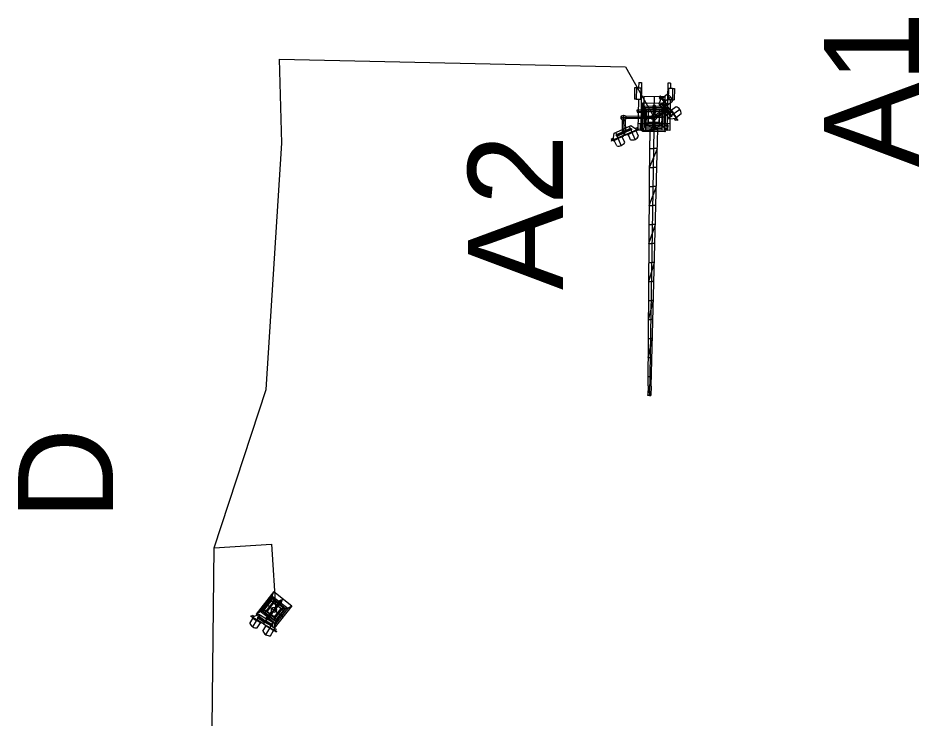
# Model space of a CAD drawing. Extents: x -717079 to -715675, y -957336 to -955099.
# Drawn here: x -716685.49 to -716661.77, y -956457.54 to -956439.09 of the extents above; entities that cross this region are included whole.
import ezdxf

# ---------------------------------------------------------------- set-up
doc = ezdxf.new("R2010")
doc.units = 0
doc.layers.add('TZ_PUPFL', color=7, linetype='Continuous')

msp = doc.modelspace()

# ---------------------------------------------------------------- linework, layer by layer
at = {"layer": 'TZ_PUPFL'}
for p, q in [((-716669.151, -956440.79), (-716669.154, -956440.93)), ((-716669.151, -956440.79), (-716669.076, -956440.791)), ((-716669.076, -956440.791), (-716669.097, -956442.041)), ((-716668.387, -956440.803), (-716668.408, -956442.052)), ((-716668.311, -956440.804), (-716668.387, -956440.803)), ((-716668.311, -956440.804), (-716668.314, -956440.944)), ((-716669.259, -956440.928), (-716669.264, -956441.228)), ((-716669.209, -956440.929), (-716669.259, -956440.928)), ((-716669.209, -956440.929), (-716669.214, -956441.229)), ((-716669.209, -956440.929), (-716669.099, -956440.931)), ((-716669.099, -956440.931), (-716669.104, -956441.231)), ((-716668.369, -956440.943), (-716668.374, -956441.243)), ((-716668.259, -956440.945), (-716668.369, -956440.943)), ((-716668.259, -956440.945), (-716668.264, -956441.245)), ((-716668.259, -956440.945), (-716668.209, -956440.946)), ((-716668.209, -956440.946), (-716668.214, -956441.246)), ((-716669.214, -956441.229), (-716669.264, -956441.228)), ((-716669.214, -956441.229), (-716669.104, -956441.231)), ((-716669.159, -956441.23), (-716669.172, -956442.04)), ((-716669.012, -956441.152), (-716669.021, -956441.692)), ((-716669.012, -956441.152), (-716668.462, -956441.161)), ((-716668.75, -956441.907), (-716668.737, -956441.157)), ((-716668.558, -956441.19), (-716668.625, -956441.363)), ((-716668.575, -956441.166), (-716668.612, -956441.193)), ((-716668.612, -956441.193), (-716668.577, -956441.24)), ((-716668.302, -956441.177), (-716668.601, -956441.395)), ((-716668.594, -956441.142), (-716668.59, -956441.139)), ((-716668.358, -956441.465), (-716668.594, -956441.142)), ((-716668.354, -956441.462), (-716668.59, -956441.139)), ((-716668.555, -956441.187), (-716668.542, -956441.179)), ((-716668.542, -956441.179), (-716668.46, -956441.292)), ((-716668.4, -956441.106), (-716668.528, -956441.199)), ((-716668.462, -956441.161), (-716668.471, -956441.701)), ((-716668.264, -956441.245), (-716668.374, -956441.243)), ((-716668.319, -956441.244), (-716668.332, -956442.054)), ((-716668.264, -956441.245), (-716668.214, -956441.246)), ((-716669.189, -956441.539), (-716669.188, -956441.509)), ((-716669.188, -956441.509), (-716669.018, -956441.512)), ((-716669.053, -956442.076), (-716669.04, -956441.327)), ((-716669.04, -956441.327), (-716668.44, -956441.337)), ((-716669.002, -956441.442), (-716669.04, -956441.327)), ((-716669.017, -956441.402), (-716668.467, -956441.411)), ((-716669.011, -956441.962), (-716669.002, -956441.442)), ((-716669.002, -956441.442), (-716668.782, -956441.446)), ((-716668.963, -956441.483), (-716669.002, -956441.442)), ((-716668.97, -956441.923), (-716668.963, -956441.483)), ((-716668.963, -956441.483), (-716668.778, -956441.486)), ((-716668.946, -956441.693), (-716668.944, -956441.523)), ((-716668.923, -956441.504), (-716668.563, -956441.51)), ((-716668.9, -956441.904), (-716668.893, -956441.504)), ((-716668.9, -956441.904), (-716668.893, -956441.504)), ((-716668.782, -956441.446), (-716668.761, -956441.389)), ((-716668.782, -956441.446), (-716668.765, -956441.631)), ((-716668.761, -956441.389), (-716668.765, -956441.631)), ((-716668.721, -956441.39), (-716668.761, -956441.389)), ((-716668.753, -956442.082), (-716668.74, -956441.332)), ((-716668.752, -956442.047), (-716668.741, -956441.373)), ((-716668.721, -956441.39), (-716668.725, -956441.632)), ((-716668.702, -956441.447), (-716668.725, -956441.632)), ((-716668.722, -956441.645), (-716668.44, -956441.475)), ((-716668.702, -956441.447), (-716668.721, -956441.39)), ((-716668.707, -956441.487), (-716668.523, -956441.491)), ((-716668.702, -956441.451), (-716668.482, -956441.451)), ((-716668.69, -956441.672), (-716668.385, -956441.489)), ((-716668.625, -956441.363), (-716668.484, -956441.556)), ((-716668.6, -956441.909), (-716668.593, -956441.509)), ((-716668.6, -956441.909), (-716668.593, -956441.509)), ((-716668.553, -956441.36), (-716668.435, -956441.521)), ((-716668.289, -956441.687), (-716668.548, -956441.332)), ((-716668.523, -956441.491), (-716668.53, -956441.931)), ((-716668.482, -956441.451), (-716668.523, -956441.491)), ((-716668.521, -956441.336), (-716668.403, -956441.498)), ((-716668.482, -956441.451), (-716668.491, -956441.971)), ((-716668.484, -956441.556), (-716668.354, -956441.462)), ((-716668.44, -956441.337), (-716668.482, -956441.451)), ((-716668.298, -956441.524), (-716668.468, -956441.521)), ((-716668.377, -956441.405), (-716668.46, -956441.292)), ((-716668.453, -956442.087), (-716668.44, -956441.337)), ((-716668.398, -956441.544), (-716668.44, -956441.475)), ((-716668.317, -956441.683), (-716668.435, -956441.521)), ((-716668.285, -956441.659), (-716668.403, -956441.498)), ((-716668.265, -956441.292), (-716668.392, -956441.385)), ((-716668.39, -956441.414), (-716668.377, -956441.405)), ((-716668.067, -956441.5), (-716668.366, -956441.718)), ((-716668.358, -956441.465), (-716668.122, -956441.788)), ((-716668.354, -956441.462), (-716668.119, -956441.785)), ((-716668.319, -956441.511), (-716668.307, -956441.502)), ((-716668.307, -956441.502), (-716668.224, -956441.615)), ((-716668.299, -956441.554), (-716668.298, -956441.524)), ((-716668.165, -956441.429), (-716668.292, -956441.522)), ((-716668.68, -956441.706), (-716669.613, -956441.717)), ((-716669.613, -956441.717), (-716669.48, -956441.716)), ((-716669.547, -956441.65), (-716669.541, -956442.139)), ((-716669.546, -956441.783), (-716669.547, -956441.65)), ((-716668.812, -956441.678), (-716669.488, -956441.686)), ((-716668.811, -956441.738), (-716669.487, -956441.746)), ((-716669.189, -956441.539), (-716668.299, -956441.554)), ((-716669.189, -956441.539), (-716669.189, -956441.569)), ((-716669.189, -956441.569), (-716669.019, -956441.572)), ((-716669.165, -956441.54), (-716668.325, -956441.554)), ((-716668.447, -956441.712), (-716669.046, -956441.702)), ((-716668.812, -956441.696), (-716669.021, -956441.692)), ((-716668.95, -956441.883), (-716668.946, -956441.693)), ((-716668.947, -956441.703), (-716668.547, -956441.71)), ((-716668.947, -956441.703), (-716668.547, -956441.71)), ((-716668.544, -956441.56), (-716668.944, -956441.553)), ((-716668.944, -956441.553), (-716668.544, -956441.56)), ((-716668.889, -956441.824), (-716668.886, -956441.694)), ((-716668.69, -956441.672), (-716668.804, -956441.741)), ((-716668.794, -956441.66), (-716668.798, -956441.657)), ((-716668.793, -956441.754), (-716668.797, -956441.758)), ((-716668.712, -956441.764), (-716668.781, -956441.65)), ((-716668.725, -956441.632), (-716668.765, -956441.631)), ((-716668.746, -956441.773), (-716668.747, -956441.64)), ((-716668.686, -956441.663), (-716668.693, -956441.667)), ((-716668.679, -956441.674), (-716668.686, -956441.678)), ((-716668.471, -956441.701), (-716668.681, -956441.698)), ((-716668.68, -956441.714), (-716668.398, -956441.544)), ((-716668.609, -956441.829), (-716668.606, -956441.699)), ((-716668.546, -956441.7), (-716668.55, -956441.89)), ((-716668.544, -956441.53), (-716668.546, -956441.7)), ((-716668.342, -956441.75), (-716668.484, -956441.556)), ((-716668.299, -956441.584), (-716668.469, -956441.581)), ((-716668.158, -956441.74), (-716668.342, -956441.75)), ((-716668.299, -956441.554), (-716668.299, -956441.584)), ((-716668.142, -956441.728), (-716668.224, -956441.615)), ((-716668.177, -956441.79), (-716668.211, -956441.743)), ((-716668.029, -956441.615), (-716668.157, -956441.708)), ((-716668.154, -956441.737), (-716668.142, -956441.728)), ((-716669.586, -956441.77), (-716669.582, -956442.099)), ((-716669.354, -956441.93), (-716669.574, -956442.026)), ((-716669.552, -956441.791), (-716669.552, -956441.783)), ((-716669.539, -956441.791), (-716669.539, -956441.783)), ((-716669.506, -956441.769), (-716669.502, -956442.098)), ((-716669.243, -956442.285), (-716669.39, -956441.946)), ((-716669.2, -956442.033), (-716669.354, -956441.93)), ((-716669.191, -956441.98), (-716669.244, -956442.003)), ((-716669.173, -956442.021), (-716669.191, -956441.98)), ((-716669.169, -956441.86), (-716668.749, -956441.867)), ((-716669.113, -956441.891), (-716669.115, -956442.021)), ((-716669.113, -956441.891), (-716669.092, -956441.871)), ((-716669.011, -956441.962), (-716669.053, -956442.076)), ((-716668.97, -956441.923), (-716669.011, -956441.962)), ((-716668.791, -956441.966), (-716669.011, -956441.962)), ((-716668.786, -956441.926), (-716668.97, -956441.923)), ((-716668.967, -956442.043), (-716668.964, -956441.873)), ((-716668.964, -956441.873), (-716668.944, -956441.873)), ((-716668.549, -956441.86), (-716668.949, -956441.853)), ((-716668.949, -956441.853), (-716668.549, -956441.86)), ((-716668.816, -956441.986), (-716668.944, -956441.873)), ((-716668.57, -956441.91), (-716668.93, -956441.904)), ((-716668.889, -956441.824), (-716668.609, -956441.829)), ((-716668.817, -956442.006), (-716668.816, -956441.986)), ((-716668.791, -956441.966), (-716668.768, -956441.781)), ((-716668.791, -956441.966), (-716668.772, -956442.024)), ((-716668.772, -956442.024), (-716668.768, -956441.781)), ((-716668.728, -956441.782), (-716668.768, -956441.781)), ((-716668.329, -956441.874), (-716668.749, -956441.867)), ((-716668.732, -956442.025), (-716668.728, -956441.782)), ((-716668.711, -956441.967), (-716668.732, -956442.025)), ((-716668.711, -956441.967), (-716668.728, -956441.782)), ((-716668.53, -956441.931), (-716668.715, -956441.927)), ((-716668.491, -956441.971), (-716668.711, -956441.967)), ((-716668.687, -956442.008), (-716668.686, -956441.988)), ((-716668.686, -956441.988), (-716668.554, -956441.88)), ((-716668.534, -956441.88), (-716668.554, -956441.88)), ((-716668.537, -956442.05), (-716668.534, -956441.88)), ((-716668.53, -956441.931), (-716668.491, -956441.971)), ((-716668.491, -956441.971), (-716668.453, -956442.087)), ((-716668.387, -956441.903), (-716668.406, -956441.882)), ((-716668.387, -956441.903), (-716668.389, -956442.033)), ((-716668.14, -956441.763), (-716668.177, -956441.79)), ((-716668.122, -956441.788), (-716668.119, -956441.785)), ((-716669.512, -956442.168), (-716669.879, -956442.327)), ((-716669.51, -956442.172), (-716669.877, -956442.332)), ((-716669.824, -956442.304), (-716669.794, -956442.121)), ((-716669.794, -956442.121), (-716669.574, -956442.026)), ((-716669.61, -956442.445), (-716669.757, -956442.105)), ((-716669.744, -956442.187), (-716669.34, -956442.011)), ((-716669.733, -956442.16), (-716669.55, -956442.081)), ((-716669.717, -956442.197), (-716669.534, -956442.117)), ((-716669.559, -956442.21), (-716669.687, -956442.266)), ((-716669.582, -956442.099), (-716669.502, -956442.098)), ((-716669.519, -956442.364), (-716669.582, -956442.22)), ((-716669.574, -956442.026), (-716669.51, -956442.172)), ((-716669.565, -956442.196), (-716669.559, -956442.21)), ((-716669.366, -956442.001), (-716669.55, -956442.081)), ((-716669.35, -956442.038), (-716669.534, -956442.117)), ((-716669.512, -956442.168), (-716669.145, -956442.009)), ((-716669.51, -956442.172), (-716669.143, -956442.013)), ((-716669.455, -956442.148), (-716669.449, -956442.162)), ((-716669.449, -956442.162), (-716669.321, -956442.106)), ((-716669.363, -956442.297), (-716669.426, -956442.152)), ((-716669.192, -956442.051), (-716669.321, -956442.106)), ((-716669.152, -956442.205), (-716669.215, -956442.061)), ((-716669.198, -956442.037), (-716669.192, -956442.051)), ((-716668.332, -956442.054), (-716669.172, -956442.04)), ((-716669.145, -956442.009), (-716669.143, -956442.013)), ((-716669.115, -956442.021), (-716669.095, -956442.041)), ((-716668.453, -956442.087), (-716669.053, -956442.076)), ((-716668.752, -956442.007), (-716668.868, -956449.026)), ((-716668.857, -956442.025), (-716668.862, -956442.325)), ((-716668.647, -956442.028), (-716668.857, -956442.025)), ((-716668.732, -956442.025), (-716668.772, -956442.024)), ((-716668.652, -956442.328), (-716668.647, -956442.028)), ((-716668.389, -956442.033), (-716668.409, -956442.052)), ((-716669.879, -956442.327), (-716669.877, -956442.332)), ((-716669.869, -956442.274), (-716669.815, -956442.251)), ((-716669.851, -956442.315), (-716669.869, -956442.274)), ((-716669.822, -956442.308), (-716669.816, -956442.321)), ((-716669.816, -956442.321), (-716669.687, -956442.266)), ((-716669.73, -956442.456), (-716669.793, -956442.312)), ((-716668.904, -956448.775), (-716668.862, -956442.325)), ((-716668.824, -956448.776), (-716668.652, -956442.328)), ((-716668.866, -956443.025), (-716668.657, -956442.528)), ((-716668.863, -956442.525), (-716668.76, -956442.527)), ((-716668.657, -956442.528), (-716668.76, -956442.527)), ((-716668.866, -956443.025), (-716668.769, -956443.027)), ((-716668.671, -956443.028), (-716668.769, -956443.027)), ((-716668.873, -956444.025), (-716668.684, -956443.528)), ((-716668.87, -956443.525), (-716668.777, -956443.526)), ((-716668.684, -956443.528), (-716668.777, -956443.526)), ((-716668.873, -956444.025), (-716668.785, -956444.026)), ((-716668.697, -956444.028), (-716668.785, -956444.026)), ((-716668.88, -956445.025), (-716668.711, -956444.528)), ((-716668.876, -956444.525), (-716668.793, -956444.526)), ((-716668.711, -956444.528), (-716668.793, -956444.526)), ((-716668.88, -956445.025), (-716668.802, -956445.026)), ((-716668.724, -956445.028), (-716668.802, -956445.026)), ((-716668.886, -956446.025), (-716668.737, -956445.527)), ((-716668.883, -956445.525), (-716668.81, -956445.526)), ((-716668.737, -956445.527), (-716668.81, -956445.526)), ((-716668.886, -956446.025), (-716668.818, -956446.026)), ((-716668.751, -956446.027), (-716668.818, -956446.026)), ((-716668.893, -956447.025), (-716668.764, -956446.527)), ((-716668.889, -956446.525), (-716668.827, -956446.526)), ((-716668.764, -956446.527), (-716668.827, -956446.526)), ((-716668.893, -956447.025), (-716668.835, -956447.026)), ((-716668.777, -956447.027), (-716668.835, -956447.026)), ((-716668.899, -956448.025), (-716668.791, -956447.527)), ((-716668.896, -956447.525), (-716668.843, -956447.526)), ((-716668.791, -956447.527), (-716668.843, -956447.526)), ((-716668.899, -956448.025), (-716668.852, -956448.026)), ((-716668.804, -956448.027), (-716668.852, -956448.026)), ((-716668.908, -956449.025), (-716668.818, -956448.526)), ((-716668.903, -956448.525), (-716668.86, -956448.526)), ((-716668.818, -956448.526), (-716668.86, -956448.526)), ((-716668.904, -956448.775), (-716668.908, -956449.025)), ((-716668.824, -956448.776), (-716668.828, -956449.026)), ((-716668.868, -956449.026), (-716668.908, -956449.025)), ((-716668.868, -956449.026), (-716668.828, -956449.026)), ((-716678.759, -956454.187), (-716679.221, -956454.778)), ((-716679.119, -956454.712), (-716678.798, -956454.302)), ((-716678.798, -956454.302), (-716678.759, -956454.187)), ((-716678.798, -956454.302), (-716678.625, -956454.438)), ((-716678.791, -956454.358), (-716678.798, -956454.302)), ((-716678.759, -956454.187), (-716678.286, -956454.557)), ((-716679.062, -956454.705), (-716678.791, -956454.358)), ((-716679.022, -956454.686), (-716678.8, -956454.402)), ((-716678.749, -956454.417), (-716678.995, -956454.732)), ((-716678.749, -956454.417), (-716678.995, -956454.732)), ((-716678.99, -956454.482), (-716678.517, -956454.852)), ((-716678.523, -956454.372), (-716678.985, -956454.963)), ((-716678.762, -956454.483), (-716678.934, -956454.704)), ((-716678.911, -956454.544), (-716678.596, -956454.79)), ((-716678.63, -956454.51), (-716678.877, -956454.825)), ((-716678.819, -956454.426), (-716678.504, -956454.672)), ((-716678.819, -956454.426), (-716678.504, -956454.672)), ((-716678.791, -956454.358), (-716678.646, -956454.472)), ((-716678.772, -956454.399), (-716678.623, -956454.516)), ((-716678.762, -956454.483), (-716678.667, -956454.557)), ((-716678.286, -956454.557), (-716678.748, -956455.147)), ((-716678.574, -956454.405), (-716678.723, -956454.596)), ((-716678.625, -956454.438), (-716678.723, -956454.596)), ((-716678.542, -956454.429), (-716678.692, -956454.62)), ((-716678.562, -956454.487), (-716678.692, -956454.62)), ((-716678.573, -956454.631), (-716678.667, -956454.557)), ((-716678.625, -956454.438), (-716678.574, -956454.405)), ((-716678.623, -956454.516), (-716678.489, -956454.62)), ((-716678.59, -956454.516), (-716678.445, -956454.629)), ((-716678.574, -956454.405), (-716678.542, -956454.429)), ((-716678.562, -956454.487), (-716678.542, -956454.429)), ((-716678.562, -956454.487), (-716678.389, -956454.623)), ((-716678.389, -956454.623), (-716678.286, -956454.557)), ((-716679.345, -956454.845), (-716679.323, -956454.806)), ((-716679.323, -956454.806), (-716679.272, -956454.836)), ((-716679.32, -956454.86), (-716679.155, -956454.777)), ((-716679.309, -956455.116), (-716679.12, -956454.798)), ((-716679.221, -956454.778), (-716679.119, -956454.712)), ((-716678.748, -956455.147), (-716679.221, -956454.778)), ((-716679.155, -956454.777), (-716678.948, -956454.9)), ((-716679.119, -956454.712), (-716679.062, -956454.705)), ((-716678.943, -956454.845), (-716679.119, -956454.712)), ((-716678.917, -956454.818), (-716679.062, -956454.705)), ((-716678.869, -956454.831), (-716679.019, -956454.714)), ((-716679.004, -956454.662), (-716678.688, -956454.909)), ((-716679.004, -956454.662), (-716678.688, -956454.909)), ((-716678.965, -956454.905), (-716678.816, -956454.714)), ((-716678.945, -956454.847), (-716678.816, -956454.714)), ((-716678.934, -956454.704), (-716678.84, -956454.777)), ((-716678.933, -956454.93), (-716678.784, -956454.739)), ((-716678.882, -956454.897), (-716678.784, -956454.739)), ((-716678.745, -956454.851), (-716678.84, -956454.777)), ((-716678.816, -956454.714), (-716678.784, -956454.739)), ((-716678.512, -956454.602), (-716678.759, -956454.917)), ((-716678.512, -956454.602), (-716678.759, -956454.917)), ((-716678.573, -956454.631), (-716678.745, -956454.851)), ((-716678.723, -956454.596), (-716678.692, -956454.62)), ((-716678.445, -956454.629), (-716678.716, -956454.976)), ((-716678.389, -956454.623), (-716678.709, -956455.032)), ((-716678.485, -956454.649), (-716678.707, -956454.932)), ((-716678.445, -956454.629), (-716678.389, -956454.623)), ((-716679.389, -956455.025), (-716679.309, -956454.89)), ((-716679.372, -956454.83), (-716679.374, -956454.833)), ((-716679.03, -956455.037), (-716679.374, -956454.833)), ((-716679.028, -956455.033), (-716679.372, -956454.83)), ((-716679.322, -956454.864), (-716679.33, -956454.877)), ((-716679.33, -956454.877), (-716679.21, -956454.948)), ((-716679.089, -956455.02), (-716679.21, -956454.948)), ((-716679.191, -956455.142), (-716679.111, -956455.007)), ((-716679.178, -956454.856), (-716678.8, -956455.081)), ((-716679.171, -956454.884), (-716678.999, -956454.986)), ((-716679.151, -956454.849), (-716678.979, -956454.951)), ((-716679.082, -956455.007), (-716679.089, -956455.02)), ((-716678.948, -956454.9), (-716679.03, -956455.037)), ((-716679.03, -956455.037), (-716678.686, -956455.241)), ((-716679.028, -956455.033), (-716678.684, -956455.237)), ((-716678.827, -956455.088), (-716678.999, -956454.986)), ((-716678.807, -956455.053), (-716678.979, -956454.951)), ((-716678.945, -956454.847), (-716678.965, -956454.905)), ((-716678.965, -956454.905), (-716678.933, -956454.93)), ((-716678.965, -956455.32), (-716678.776, -956455.002)), ((-716678.742, -956455.022), (-716678.948, -956454.9)), ((-716678.882, -956454.897), (-716678.933, -956454.93)), ((-716678.709, -956455.032), (-716678.882, -956454.897)), ((-716678.735, -956454.936), (-716678.869, -956454.831)), ((-716678.716, -956454.976), (-716678.861, -956454.862)), ((-716678.709, -956455.032), (-716678.748, -956455.147)), ((-716678.735, -956455.207), (-716678.742, -956455.022)), ((-716678.716, -956454.976), (-716678.709, -956455.032)), ((-716679.045, -956455.229), (-716678.964, -956455.094)), ((-716678.978, -956455.068), (-716678.986, -956455.081)), ((-716678.986, -956455.081), (-716678.866, -956455.152)), ((-716678.745, -956455.224), (-716678.866, -956455.152)), ((-716678.847, -956455.346), (-716678.767, -956455.211)), ((-716678.737, -956455.211), (-716678.745, -956455.224)), ((-716678.687, -956455.183), (-716678.737, -956455.153)), ((-716678.71, -956455.222), (-716678.687, -956455.183)), ((-716678.684, -956455.237), (-716678.686, -956455.241))]:
    msp.add_line(p, q, dxfattribs=at)
for points in [[(-716682.682, -956485.549), (-716684.309, -956485.117), (-716683.726, -956482.879), (-716679.632, -956479.652), (-716679.258, -956477.256), (-716679.479, -956475.115), (-716680.551, -956472.706), (-716680.325, -956453.033), (-716678.96, -956448.869), (-716678.546, -956442.387), (-716678.608, -956440.175), (-716669.501, -956440.378), (-716668.747, -956441.71)], [(-716669.092, -956441.871), (-716668.964, -956441.873)], [(-716668.406, -956441.882), (-716668.534, -956441.88)], [(-716669.095, -956442.041), (-716668.752, -956442.047)], [(-716668.967, -956442.003), (-716668.752, -956442.007)], [(-716668.537, -956442.01), (-716668.752, -956442.007)], [(-716668.409, -956442.052), (-716668.752, -956442.047)], [(-716682.682, -956485.549), (-716684.309, -956485.117), (-716683.726, -956482.879), (-716679.632, -956479.652), (-716679.258, -956477.256), (-716679.479, -956475.115), (-716680.551, -956472.706), (-716680.325, -956453.033), (-716678.816, -956452.936), (-716678.701, -956454.708)]]:
    msp.add_lwpolyline(points, dxfattribs=at)
for centre, radius in [((-716668.537, -956441.348), 0.02), ((-716669.547, -956441.716), 0.0665), ((-716668.894, -956441.554), 0.0135), ((-716668.747, -956441.707), 0.0665), ((-716668.594, -956441.559), 0.0135), ((-716668.301, -956441.671), 0.02), ((-716669.081, -956441.996), 0.012), ((-716669.08, -956441.916), 0.012), ((-716668.899, -956441.854), 0.0135), ((-716668.599, -956441.859), 0.0135), ((-716668.421, -956442.007), 0.012), ((-716668.42, -956441.927), 0.012), ((-716669.725, -956442.179), 0.02), ((-716669.358, -956442.019), 0.02), ((-716678.779, -956454.457), 0.0135), ((-716678.964, -956454.693), 0.0135), ((-716678.754, -956454.667), 0.0665), ((-716678.543, -956454.641), 0.0135), ((-716679.161, -956454.867), 0.02), ((-716678.728, -956454.878), 0.0135), ((-716678.817, -956455.07), 0.02)]:
    msp.add_circle(centre, radius, dxfattribs=at)
for centre, radius, start, end in [((-716668.46, -956441.292), 0.195, 36.0884, 72.2272), ((-716668.46, -956441.292), 0.195, 359.9496, 36.0884), ((-716668.924, -956441.524), 0.02, 89.0486, 179.0486), ((-716668.564, -956441.53), 0.02, 359.0486, 89.0486), ((-716668.419, -956441.509), 0.04, 301.0656, 121.0656), ((-716668.224, -956441.615), 0.195, 36.0884, 72.2272), ((-716668.224, -956441.615), 0.195, 359.9496, 36.0884), ((-716668.747, -956441.707), 0.0715, 135.6942, 225.6944), ((-716668.747, -956441.707), 0.0665, 135.6941, 225.6944), ((-716668.747, -956441.707), 0.0665, 354.0879, 68.0433), ((-716668.747, -956441.707), 0.075, 31.0656, 63.2965), ((-716668.747, -956441.707), 0.075, 358.8346, 31.0656), ((-716669.547, -956441.716), 0.0665, 233.7168, 307.6721), ((-716669.547, -956441.716), 0.075, 238.4635, 270.6945), ((-716669.547, -956441.716), 0.075, 270.6945, 302.9254), ((-716668.93, -956441.884), 0.02, 179.0486, 269.0486), ((-716668.57, -956441.89), 0.02, 269.0486, 359.0486), ((-716669.542, -956442.099), 0.04, 180.6945, 0.6945), ((-716669.321, -956442.106), 0.195, 293.476, 329.6148), ((-716669.687, -956442.266), 0.195, 257.3372, 293.476), ((-716669.687, -956442.266), 0.195, 293.476, 329.6148), ((-716669.321, -956442.106), 0.195, 257.3372, 293.476), ((-716678.784, -956454.414), 0.02, 51.9759, 141.9759), ((-716679.006, -956454.698), 0.02, 141.9759, 231.9759), ((-716678.501, -956454.636), 0.02, 321.9759, 51.9759), ((-716679.21, -956454.948), 0.195, 203.2173, 239.3561), ((-716678.723, -956454.92), 0.02, 231.9759, 321.9759), ((-716679.21, -956454.948), 0.195, 239.3561, 275.495), ((-716678.866, -956455.152), 0.195, 203.2173, 239.3561), ((-716678.866, -956455.152), 0.195, 239.3561, 275.495)]:
    msp.add_arc(centre, radius, start, end, dxfattribs=at)

# ---------------------------------------------------------------- texts
for s, height, rotation, p in [('A1', 2.5, 90, (-716661.772, -956443.018)), ('TIZ', 0.02, 179, (-716668.763, -956442.052)), ('A2', 2.5, 90, (-716671.146, -956446.247)), ('D', 2.5, 90, (-716682.991, -956452.295)), ('TIZ', 0.02, 321.9759, (-716678.533, -956454.402))]:
    msp.add_text(s, height=height, rotation=rotation, dxfattribs=at).set_placement(p)

doc.saveas('drawing.dxf')
